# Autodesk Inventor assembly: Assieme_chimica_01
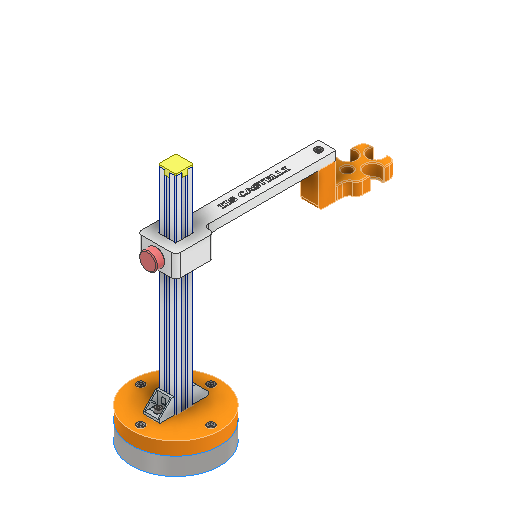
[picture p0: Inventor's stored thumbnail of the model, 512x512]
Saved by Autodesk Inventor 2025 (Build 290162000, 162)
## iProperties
Created: 2025-09
Part Number: Assieme_chimica_01
Document SubType Name: Assembly
Designer: Ryzen5700u
Author: Ryzen5700u
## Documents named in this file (16)
- C:\Users\18907419\Desktop\pack\Assieme_chimica_01.iam
- C:\Users\18907419\Desktop\pack\tslot-20x20-3_MIR1.ipt
- C:\Users\18907419\Desktop\pack\SNSD20x20.ipt
- C:\Users\18907419\Desktop\pack\base_petg.ipt
- C:\Users\18907419\Desktop\pack\base_ferro.ipt
- C:\Users\18907419\Desktop\pack\braccio.ipt
- C:\Users\18907419\Desktop\pack\tappo_2020.ipt
- C:\Users\18907419\Desktop\pack\vite_blocco.ipt
- C:\Users\18907419\Desktop\pack\porta_sensore.ipt
- C:\Users\18907419\Documents\Inventor\Content Center Files\R2025\it-IT\AS 1420\AS 1420 - 1973 - M5 x 20.ipt
- C:\Users\18907419\Documents\Inventor\Content Center Files\R2025\it-IT\AS 1112 (2)\AS 1112 - M4  Tipo 5.ipt
- C:\Users\18907419\Documents\Inventor\Content Center Files\R2025\it-IT\AS 1420\AS 1420 - 1973 - M4 x 8.ipt
- C:\Users\18907419\Documents\Inventor\Content Center Files\R2025\it-IT\AS 1420\AS 1420 - 1973 - M5 x 35.ipt
- C:\Users\18907419\Documents\Inventor\Content Center Files\R2025\it-IT\AS 1420\AS 1420 - 1973 - M4 x 16.ipt
- C:\Users\18907419\Documents\Inventor\Content Center Files\R2025\it-IT\AS 1420\AS 1420 - 1973 - M4 x 30.ipt
- C:\Users\18907419\Desktop\pack\Slider T-Nut for 2020 - M4.ipt
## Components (22 placed, 15 different names)
1. tslot-20x20-3_MIR1:1
2. SNSD20x20:1 — Allineato:1, Allineato:2, Coincidente:1, Coincidente:16
3. SNSD20x20:2 — Allineato:3, Coincidente:2, Allineato:4, Coincidente:13, Coincidente:15
4. base_petg:1
5. base_ferro:1 — Allineato:6
6. braccio:1
7. tappo_2020:1 — Allineato:8
8. vite_blocco:1 — Allineato:9, Coincidente:22
9. porta_sensore:1 — Allineato:10, Coincidente:23, Angolo:2, Rotazionale:3
10. AS 1420 - Metrico M5 x 20:1 — Coincidente:6
11. AS 1420 - Metrico M5 x 20:2 — Coincidente:8
12. AS 1420 - Metrico M5 x 20:3 — Coincidente:10
13. AS 1420 - Metrico M5 x 20:4 — Coincidente:12
14. AS 1112 (2) - Metrico M4  Tipo 5:1
15. AS 1112 (2) - Metrico M4  Tipo 5:2
16. AS 1420 - Metrico M4 x 16:2 — Coincidente:13, Coincidente:14
17. AS 1420 - Metrico M5 x 35:1 — Rotazionale:1
18. AS 1420 - Metrico M4 x 8:4 — Coincidente:15
19. AS 1420 - Metrico M4 x 16:1 — Coincidente:16, Coincidente:17
20. AS 1112 (2) - Metrico M4  Tipo 5:3 — Rotazionale:3
21. AS 1420 - Metrico M4 x 30:1 — Rotazionale:2, Coincidente:23
22. Slider T-Nut for 2020 - M4:1 — Angolo:1, Coincidente:19, Coincidente:20, Coincidente:21
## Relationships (29: Mate 16, Flush 8, RevoluteJoint 3, Angle 2)
- Allineato:1 [Flush]: SNSD20x20:1
- Allineato:2 [Flush]: SNSD20x20:1
- Coincidente:1 [Mate]: SNSD20x20:1
- Allineato:3 [Flush]: SNSD20x20:2
- Coincidente:2 [Mate]: SNSD20x20:2
- Allineato:4 [Flush]: SNSD20x20:2
- Allineato:6 [Flush]: base_ferro:1
- Allineato:8 [Flush]: tappo_2020:1
- Allineato:9 [Flush]: vite_blocco:1
- Allineato:10 [Flush]: porta_sensore:1
- Coincidente:6 [Mate]: AS 1420 - Metrico M5 x 20:1
- Coincidente:8 [Mate]: AS 1420 - Metrico M5 x 20:2
- Coincidente:10 [Mate]: AS 1420 - Metrico M5 x 20:3
- Coincidente:12 [Mate]: AS 1420 - Metrico M5 x 20:4
- Coincidente:13 [Mate]: SNSD20x20:2 ↔ AS 1420 - Metrico M4 x 16:2
- Coincidente:14 [Mate]: AS 1420 - Metrico M4 x 16:2
- Rotazionale:1 [RevoluteJoint]: AS 1420 - Metrico M5 x 35:1
- Coincidente:15 [Mate]: SNSD20x20:2 ↔ AS 1420 - Metrico M4 x 8:4
- Coincidente:16 [Mate]: SNSD20x20:1 ↔ AS 1420 - Metrico M4 x 16:1
- Coincidente:17 [Mate]: AS 1420 - Metrico M4 x 16:1
- Rotazionale:2 [RevoluteJoint]: AS 1420 - Metrico M4 x 30:1
- Angolo:1 [Angle]: Slider T-Nut for 2020 - M4:1
- Coincidente:19 [Mate]: Slider T-Nut for 2020 - M4:1
- Coincidente:20 [Mate]: Slider T-Nut for 2020 - M4:1
- Coincidente:21 [Mate]: Slider T-Nut for 2020 - M4:1
- Coincidente:22 [Mate]: vite_blocco:1
- Coincidente:23 [Mate]: porta_sensore:1 ↔ AS 1420 - Metrico M4 x 30:1
- Angolo:2 [Angle]: porta_sensore:1
- Rotazionale:3 [RevoluteJoint]: porta_sensore:1 ↔ AS 1112 (2) - Metrico M4  Tipo 5:3
